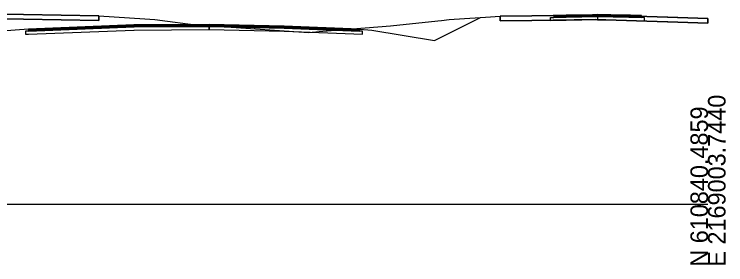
# Model space of a CAD drawing. Extents: x -26 to 1303, y -3010 to 12038.
# Drawn here: x 1189.2 to 1302.8, y 8490.3 to 8530.3 of the extents above; entities that cross this region are included whole.
import ezdxf

# ---------------------------------------------------------------- set-up
doc = ezdxf.new("R2010")
doc.units = 0
for name, color, linetype in [('RD_GPK_XS_Cell', 7, 'Continuous'), ('RD_XS_Base', 7, 'Continuous'), ('RD_XS_ExGround', 7, 'Continuous'), ('RD_XS_ExPaveRet', 7, 'Continuous'), ('RD_XS_Greenside', 7, 'Continuous'), ('RD_XS_Pave', 7, 'Continuous'), ('RD_XS_PaveOvlay_CP', 7, 'Continuous'), ('RD_XS_TieSlope', 7, 'Continuous')]:
    doc.layers.add(name, color=color, linetype=linetype)

msp = doc.modelspace()

# ---------------------------------------------------------------- linework, layer by layer
at = {"layer": 'RD_GPK_XS_Cell'}
msp.add_line((1150, 8500), (1300, 8500), dxfattribs=at)
at = {"layer": 'RD_XS_Base'}
for p, q in [((1282.36, 8530.1), (1282.36, 8530.12)), ((1282.36, 8530.12), (1282.36, 8529.57)), ((1282.36, 8529.96), (1282.36, 8530.1)), ((1274.86, 8529.81), (1275.36, 8529.82)), ((1274.86, 8529.31), (1274.86, 8529.81)), ((1275.36, 8529.32), (1274.86, 8529.31)), ((1275.36, 8529.82), (1277.36, 8529.86)), ((1277.36, 8529.36), (1275.36, 8529.32)), ((1277.36, 8529.86), (1282.36, 8529.96)), ((1282.36, 8529.46), (1277.36, 8529.36)), ((1286.63, 8529.88), (1282.36, 8529.96)), ((1282.36, 8529.96), (1282.36, 8529.46)), ((1282.36, 8529.57), (1282.36, 8529.46)), ((1282.36, 8529.46), (1286.63, 8529.38)), ((1287.36, 8529.86), (1286.63, 8529.88)), ((1286.63, 8529.38), (1287.36, 8529.36)), ((1287.65, 8529.86), (1287.36, 8529.86)), ((1287.36, 8529.36), (1287.72, 8529.36)), ((1289.36, 8529.82), (1287.65, 8529.86)), ((1287.72, 8529.36), (1289.86, 8529.31)), ((1289.43, 8529.82), (1289.36, 8529.82)), ((1289.86, 8529.81), (1289.43, 8529.82)), ((1289.86, 8529.38), (1289.86, 8529.81)), ((1289.86, 8529.31), (1289.86, 8529.38)), ((1208.33, 8528.32), (1191.5, 8527.65)), ((1191.5, 8527.15), (1208.33, 8527.82)), ((1220.33, 8528.38), (1208.33, 8528.32)), ((1208.35, 8528.32), (1208.33, 8528.32)), ((1208.33, 8527.82), (1220.33, 8527.88)), ((1208.33, 8527.82), (1208.35, 8527.82)), ((1220.33, 8528.38), (1220.33, 8528.54)), ((1220.33, 8528.54), (1220.33, 8527.88)), ((1220.33, 8527.88), (1220.33, 8528.38)), ((1232.33, 8528.14), (1220.33, 8528.38)), ((1220.33, 8528.38), (1220.33, 8528.38)), ((1220.33, 8527.88), (1220.33, 8527.88)), ((1220.33, 8527.88), (1220.33, 8527.88)), ((1220.33, 8527.88), (1232.33, 8527.64)), ((1244.33, 8527.66), (1232.33, 8528.14)), ((1232.33, 8528.14), (1232.33, 8528.14)), ((1191.5, 8527.65), (1191, 8527.63)), ((1191, 8527.63), (1191, 8527.63)), ((1191, 8527.63), (1191, 8527.13)), ((1191, 8527.13), (1191.5, 8527.15)), ((1191, 8527.13), (1191, 8527.13)), ((1191, 8527.13), (1191, 8527.13)), ((1191.51, 8527.65), (1191.5, 8527.65)), ((1191.5, 8527.15), (1191.51, 8527.15)), ((1232.33, 8527.64), (1232.33, 8527.64)), ((1232.33, 8527.64), (1244.83, 8527.14)), ((1244.83, 8527.64), (1244.33, 8527.66)), ((1244.33, 8527.66), (1244.33, 8527.66)), ((1244.83, 8527.14), (1244.83, 8527.64)), ((1244.83, 8527.64), (1244.83, 8527.64)), ((1244.83, 8527.14), (1244.83, 8527.14)), ((1244.83, 8527.14), (1244.83, 8527.14))]:
    msp.add_line(p, q, dxfattribs=at)
at = {"layer": 'RD_XS_ExGround'}
msp.add_lwpolyline([(1187.42, 8530.34), (1190.67, 8530.29), (1202.73, 8530.1), (1210.09, 8529.6), (1211.64, 8529.49), (1218.94, 8528.55), (1219.27, 8528.51), (1220.3, 8528.5), (1220.79, 8528.47), (1236.19, 8527.43), (1238.51, 8527.62), (1249.29, 8528.48), (1256.88, 8529.3), (1257.42, 8529.36), (1258.66, 8529.5), (1259.49, 8529.55), (1264.48, 8529.88), (1266.79, 8530.02), (1271.89, 8530.09), (1282.03, 8530.25), (1293.56, 8529.88), (1300, 8529.67)], dxfattribs=at)
at = {"layer": 'RD_XS_ExPaveRet'}
for p, q in [((1293.56, 8529.88), (1282.04, 8530.25)), ((1300, 8529.67), (1300, 8528.92)), ((1300, 8528.92), (1300, 8529.67))]:
    msp.add_line(p, q, dxfattribs=at)
for points in [[(1165.67, 8529.71), (1165.67, 8528.96), (1176.77, 8529.28), (1187.42, 8529.59), (1190.67, 8529.54), (1202.73, 8529.35), (1202.73, 8530.1), (1190.67, 8530.29), (1187.42, 8530.34)], [(1187.42, 8530.34), (1190.67, 8530.29), (1190.67, 8530.29), (1202.73, 8530.1), (1202.73, 8530.1)], [(1202.73, 8530.1), (1202.73, 8529.35), (1202.73, 8529.35), (1202.73, 8529.35), (1190.67, 8529.54), (1190.67, 8529.54), (1187.42, 8529.59)], [(1300, 8528.92), (1293.58, 8529.13), (1293.56, 8529.13), (1282.04, 8529.5), (1282.03, 8529.5), (1282.02, 8529.5), (1271.89, 8529.34), (1271.88, 8529.34), (1266.79, 8529.27), (1266.79, 8530.02), (1266.79, 8530.02), (1271.88, 8530.09), (1271.89, 8530.09), (1282.02, 8530.25), (1282.03, 8530.25), (1282.04, 8530.25), (1293.56, 8529.88), (1293.58, 8529.88), (1300, 8529.67)], [(1282.02, 8530.25), (1271.89, 8530.09), (1271.88, 8530.09), (1266.79, 8530.02), (1266.79, 8530.02), (1266.79, 8529.27), (1271.88, 8529.34), (1271.89, 8529.34), (1282.02, 8529.5), (1282.03, 8529.5), (1282.04, 8529.5), (1293.56, 8529.13), (1293.58, 8529.13), (1300, 8528.92)], [(1282.04, 8530.25), (1282.03, 8530.25), (1282.02, 8530.25)], [(1300, 8529.67), (1293.58, 8529.88), (1293.56, 8529.88)]]:
    msp.add_lwpolyline(points, dxfattribs=at)
at = {"layer": 'RD_XS_Greenside'}
for p, q in [((1256.33, 8526.16), (1263.68, 8529.83)), ((1246.33, 8527.82), (1256.33, 8526.16))]:
    msp.add_line(p, q, dxfattribs=at)
at = {"layer": 'RD_XS_Pave'}
for p, q in [((1275.71, 8530.15), (1275.36, 8530.14)), ((1275.36, 8530.14), (1275.36, 8530.11)), ((1275.36, 8530.11), (1275.36, 8529.98)), ((1277.36, 8530.02), (1275.36, 8529.98)), ((1277.36, 8530.18), (1275.71, 8530.15)), ((1275.71, 8529.99), (1277.36, 8530.02)), ((1281.55, 8530.26), (1277.36, 8530.18)), ((1282.36, 8530.12), (1277.36, 8530.02)), ((1277.36, 8530.02), (1281.55, 8530.11)), ((1282.36, 8530.28), (1281.55, 8530.26)), ((1281.55, 8530.11), (1282.36, 8530.12)), ((1286.63, 8530.2), (1282.36, 8530.28)), ((1282.36, 8530.12), (1286.63, 8530.04)), ((1287.36, 8530.02), (1282.36, 8530.12)), ((1282.36, 8530.12), (1282.36, 8529.96)), ((1282.36, 8529.96), (1282.36, 8530.12)), ((1287.36, 8530.18), (1286.63, 8530.2)), ((1286.63, 8530.04), (1287.36, 8530.02)), ((1287.65, 8530.17), (1287.36, 8530.18)), ((1287.36, 8530.02), (1287.65, 8530.02)), ((1289.36, 8529.98), (1287.36, 8530.02)), ((1289.36, 8530.14), (1287.65, 8530.17)), ((1287.65, 8530.02), (1289.36, 8529.98)), ((1289.36, 8530), (1289.36, 8530.14)), ((1289.36, 8529.98), (1289.36, 8530)), ((1275.36, 8529.98), (1275.71, 8529.99)), ((1275.36, 8529.98), (1275.36, 8529.82)), ((1275.36, 8529.82), (1277.36, 8529.86)), ((1277.36, 8529.86), (1282.36, 8529.96)), ((1282.36, 8529.96), (1287.36, 8529.86)), ((1287.36, 8529.86), (1289.36, 8529.82)), ((1289.36, 8529.82), (1289.36, 8529.98)), ((1208.33, 8528.64), (1191.5, 8527.97)), ((1208.33, 8528.48), (1191.5, 8527.81)), ((1191.5, 8527.81), (1208.33, 8528.48)), ((1191.5, 8527.65), (1208.33, 8528.32)), ((1191.51, 8527.97), (1191.5, 8527.97)), ((1191.5, 8527.97), (1191.5, 8527.81)), ((1191.51, 8527.81), (1191.5, 8527.81)), ((1191.5, 8527.81), (1191.5, 8527.65)), ((1191.5, 8527.81), (1191.5, 8527.81)), ((1191.5, 8527.81), (1191.51, 8527.81)), ((1220.33, 8528.7), (1208.33, 8528.64)), ((1208.35, 8528.64), (1208.33, 8528.64)), ((1220.33, 8528.54), (1208.33, 8528.48)), ((1208.33, 8528.48), (1220.33, 8528.54)), ((1208.35, 8528.48), (1208.33, 8528.48)), ((1208.33, 8528.48), (1208.35, 8528.48)), ((1208.33, 8528.32), (1220.33, 8528.38)), ((1208.33, 8528.32), (1208.35, 8528.32)), ((1232.33, 8528.46), (1220.33, 8528.7)), ((1220.33, 8528.38), (1220.33, 8528.54)), ((1232.33, 8528.3), (1220.33, 8528.54)), ((1220.33, 8528.54), (1220.33, 8528.38)), ((1220.33, 8528.54), (1232.33, 8528.3)), ((1220.33, 8528.38), (1220.33, 8528.38)), ((1220.33, 8528.38), (1220.33, 8528.38)), ((1220.33, 8528.38), (1232.33, 8528.14)), ((1244.33, 8527.98), (1232.33, 8528.46)), ((1232.33, 8528.46), (1232.33, 8528.46)), ((1244.33, 8527.82), (1232.33, 8528.3)), ((1232.33, 8528.3), (1232.33, 8528.3)), ((1232.33, 8528.3), (1232.33, 8528.3)), ((1232.33, 8528.3), (1244.33, 8527.82)), ((1232.33, 8528.14), (1232.33, 8528.14)), ((1232.33, 8528.14), (1244.33, 8527.66)), ((1244.33, 8527.82), (1244.33, 8527.98)), ((1244.33, 8527.98), (1244.33, 8527.98)), ((1244.33, 8527.66), (1244.33, 8527.82)), ((1244.33, 8527.82), (1244.33, 8527.82)), ((1244.33, 8527.82), (1244.33, 8527.82)), ((1244.33, 8527.82), (1244.33, 8527.82)), ((1191.5, 8527.65), (1191.5, 8527.65)), ((1191.5, 8527.65), (1191.51, 8527.65)), ((1244.33, 8527.66), (1244.33, 8527.66)), ((1244.33, 8527.66), (1244.33, 8527.66))]:
    msp.add_line(p, q, dxfattribs=at)
at = {"layer": 'RD_XS_PaveOvlay_CP'}
for p, q in [((1275.36, 8530.14), (1277.36, 8530.18)), ((1277.36, 8530.18), (1282.36, 8530.28)), ((1282.36, 8530.28), (1287.36, 8530.18)), ((1287.36, 8530.18), (1289.36, 8530.14)), ((1208.33, 8528.64), (1191.5, 8527.97)), ((1191.51, 8527.97), (1191.5, 8527.97)), ((1220.33, 8528.7), (1208.33, 8528.64)), ((1208.35, 8528.64), (1208.33, 8528.64)), ((1232.33, 8528.46), (1220.33, 8528.7)), ((1244.33, 8527.98), (1232.33, 8528.46)), ((1232.33, 8528.46), (1232.33, 8528.46)), ((1244.33, 8527.98), (1244.33, 8527.98))]:
    msp.add_line(p, q, dxfattribs=at)
at = {"layer": 'RD_XS_TieSlope'}
for p, q in [((1191.5, 8527.97), (1185.5, 8527.49)), ((1244.33, 8527.98), (1246.33, 8527.82))]:
    msp.add_line(p, q, dxfattribs=at)

# ---------------------------------------------------------------- texts
at = {"layer": 'RD_GPK_XS_Cell'}
for s, p in [('E 2169003.7440', (1302.8, 8490)), ('N 610840.4859', (1300, 8490))]:
    msp.add_text(s, height=2.8, rotation=90, dxfattribs=at).set_placement(p)

doc.saveas('drawing.dxf')
